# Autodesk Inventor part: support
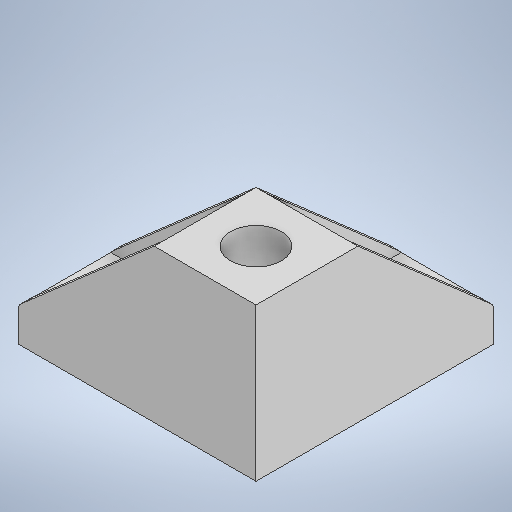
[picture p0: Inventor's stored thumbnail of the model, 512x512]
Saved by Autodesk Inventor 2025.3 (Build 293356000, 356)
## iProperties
Created: 2025-04
Part Number: support
Material: Generic
Document SubType Name: Modeling
Designer: Jarni
Density: 1 g/cm^3
Appearance: Default
Author: Jarni
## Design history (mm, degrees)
sketch "Sketch1"
  geometry: L1 (-15, 15)-(15, 15); L2 (15, 15)-(15, -15); L3 (15, -15)-(-15, -15); L4 (-15, -15)-(-15, 15); L5 (-15, 15)-(15, -15); L6 (15, 15)-(-15, -15); 1 further point
  constraints: 12 end point, 2 midpoint, 2 parallel, 1 horizontal, 1 perpendicular
  dimensions: "d0" = 30 distance of L2.end L3.end; "d1" = 30 distance of L1.end L2.end
extrude "Extrusion1" new body sketch "Sketch1" distance "d2" = 45; taper "d3" = 0 deg
sketch "Sketch2"
  geometry: C1 r 7.5 at (0, 0); 1 further point
  constraints: 1 centre point, 1 coincident
  dimensions: "d4" = 15 diameter of C1
extrude "Extrusion2" cut sketch "Sketch2" distance "d5" = 20; taper "d6" = 0 deg
sketch "Sketch4"
  geometry: C1 r 7.5 at (0, 0) reference; 2 further points
  constraints: 1 coincident
hole "Hole1" sketch "Sketch4" at (0, 0) diameter "d7" = 5.5; stored, may be unused: countersink angle "d11" = 90 deg, drill point angle "d13" = 118 deg; dims "d8" = 12.7, "d9" = 10, "d10" = 5.7, "d12" = 8
sketch "Sketch5"
  geometry: L1 (15, -15)-(-15, -15) reference; L2 (15, 15)-(15, -15) reference; L3 (-15, 15)-(15, 15) reference; L4 (-15, -15)-(-15, 15) reference; L5 (-15, -15)-(-15, 15); L6 (-15, 15)-(-55, 15); L7 (-55, 15)-(-55, -15); L8 (-55, -15)-(-15, -15); L9 (-15, -15)-(-15, 15) reference; L10 (15, -15)-(-15, -15) reference; L11 (-15, -15)-(15, -15); L12 (15, -15)-(15, -55); L13 (15, -55)-(-15, -55); L14 (-15, -55)-(-15, -15); C1 r 2.75 at (0, 0) reference; 1 further point
  constraints: 16 end point, 6 equal length, 2 perpendicular
  dimensions: "d14" = 40 distance of L6.end L3.start; "d15" = 40 distance of L1.start L12.end
extrude "Extrusion3" join sketch "Sketch5" distance "d16" = 10; taper "d17" = 0 deg
sketch "Sketch6"
  geometry: L1 (30, -45)-(-40, -45) reference; L2 (30, -45)-(30, 0) reference; L3 (0, 0)-(30, 0) reference; L4 (0, -35)-(0, 0) reference; L5 (-40, -35)-(0, -35) reference; L6 (-40, -45)-(-40, -35) reference; L7 (0, -35)-(0, -15); L8 (-20, -35)-(0, -35); L9 (-20, -35)-(0, -15); 1 further point
  constraints: 6 end point, 1 midpoint, 1 perpendicular, 1 point on line
  dimensions: "d18" = 20 distance of L7.end L4.start; "d19" = 20 distance of L4.start L8.start
extrude "Extrusion4" join sketch "Sketch6" distance "d20" = 30; taper "d21" = 0 deg
sketch "Sketch7"
  geometry: L1 (30, -35)-(0, -35) reference; L2 (0, -45)-(0, -35) reference; L3 (30, -45)-(-40, -45) reference; L4 (30, -45)-(30, 0) reference; L5 (0, 0)-(30, 0) reference; L6 (0, -15)-(0, 0) reference; L7 (0, -15)-(-20, -35) reference; L8 (-40, -35)-(-20, -35) reference; L9 (-40, -45)-(-40, -35) reference; L10 (-40, -35)-(0, 0); L11 (0, -35)-(-40, -35); L12 (0, -35)-(0, 0); 1 further point
  constraints: 6 end point, 1 collinear
extrude "Extrusion5" join sketch "Sketch7" distance "d22" = 3; taper "d23" = 0 deg
sketch "Sketch8"
  geometry: L1 (0, -45)-(70, -45) reference; L2 (0, -45)-(0, 0) reference; L3 (30, 0)-(0, 0) reference; L4 (30, 0)-(70, -35) reference; L5 (70, -45)-(70, -35) reference; L6 (30, 0)-(30, -35); L7 (30, -35)-(70, -35); L8 (30, 0)-(70, -35); 1 further point
  constraints: 6 end point, 1 collinear, 1 perpendicular, 1 vertical
extrude "Extrusion6" join sketch "Sketch8" distance "d24" = 3; taper "d25" = 0 deg
sketch "Sketch9"
  geometry: L1 (30, 10)-(70, 10) reference; L2 (7.5, 25)-(22.5, 25) reference; L3 (0, 0)-(70, 0) reference; L4 (70, 0)-(70, 10) reference; L5 (30, 10)-(70, 10) reference; L6 (30, 10)-(30, 45) reference; L7 (0, 45)-(30, 45) reference; L8 (0, 0)-(0, 45) reference; L9 (30, 10)-(50, 10); L10 (30, 30)-(50, 10); L11 (30, 10)-(30, 30); 3 further points
  constraints: 6 end point, 1 collinear, 1 midpoint, 1 point on line
  dimensions: "d26" = 20 distance of L1.start L10.start; "d27" = 20 distance of L1.start L9.end
extrude "Extrusion7" join sketch "Sketch9" distance "d28" = 30; taper "d29" = 0 deg
sketch "Sketch10"
  geometry: L1 (0, 0)-(70, 0) reference; L2 (70, 0)-(70, 10) reference; L3 (50, 10)-(70, 10) reference; L4 (50, 10)-(30, 30) reference; L5 (30, 30)-(30, 45) reference; L6 (0, 45)-(30, 45) reference; L7 (0, 0)-(0, 45) reference; L8 (30, 45)-(70, 10); L9 (30, 10)-(30, 45) reference; L10 (70, 10)-(30, 10); L11 (30, 10)-(30, 45); 2 further points
  constraints: 6 end point, 1 horizontal, 1 perpendicular
extrude "Extrusion8" join sketch "Sketch10" distance "d30" = 3; taper "d31" = 0 deg
sketch "Sketch11"
  geometry: L1 (-55, 12)-(-55, -12) reference; L2 (12, 55)-(-15, 55) reference; 3 further points
  dimensions: "d32" = 10 distance from line of L1 point (-45, 0); "d33" = 10 distance from line of L2 point (0, 45)
hole "Hole2" sketch "Sketch11" at (-45, 0), (0, 45) diameter "d34" = 5.5; stored, may be unused: countersink angle "d38" = 90 deg, drill point angle "d40" = 118 deg; dims "d35" = 6, "d36" = 10, "d37" = 5.7, "d39" = 8
sketch "Sketch12"
  geometry: L1 (70, 45)-(40, 45) reference; L2 (70, 0)-(70, 45) reference; L3 (70, 0)-(0, 0) reference; L4 (0, 0)-(0, 10) reference; L5 (0, 10)-(40, 45) reference; L6 (40, 45)-(40, 10); L7 (40, 10)-(0, 10); L8 (40, 45)-(0, 10); 1 further point
  constraints: 6 end point, 1 collinear, 1 perpendicular, 1 vertical
extrude "Extrusion9" join sketch "Sketch12" distance "d41" = 3; taper "d42" = 0 deg
fillet "Fillet1" dims "d43" = 2
body "Solid1"
node "Projected Loop1"
node "Projected Loop2"
node "Projected Loop3"
node "Projected Loop4"
node "Projected Loop5"
node "Projected Loop6"
node "Projected Loop7"
